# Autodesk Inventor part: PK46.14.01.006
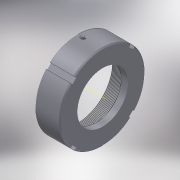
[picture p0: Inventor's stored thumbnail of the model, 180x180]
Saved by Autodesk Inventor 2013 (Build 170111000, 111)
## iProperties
Shininess: 64.0
Length Units: 11269
Angle Units: 11279
Time Units: 11290
Mass Units: 11283
Length Display Precision: 3
Angle Display Precision: 2
Compacted: True
Part Number: PK46.14.01.006
Document SubType Name: Modeling
Created: 2004-11
Material: Сталь высокопрочная низколегированная
Designer: ELarisa
Manufacturer: Standard
Standards Organization: Custom
Density: 7.84 g/cm^3
Density: 0.0
Volumn: 0.0
Area: 0.0
PropertySet Name: Model Information
Control State: 0
Master: False
Checked Out: False
Checked Out Date: 2008-10-15
Last Check In Date: 2008-10-15
Author: ELarisa
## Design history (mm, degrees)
sketch "Эскиз1"
  geometry: L1 (-22.039, -42.966)-(-22.039, 32.534); L2 (-22.039, 32.534)-(-20.039, 34.534); L3 (-20.039, 34.534)-(21.961, 34.534); L4 (21.961, 34.534)-(23.961, 32.534); L5 (23.961, 32.534)-(23.961, -42.966); L6 (23.961, -42.966)-(-22.039, -42.966); L7 (-22.039, 20.534)-(-20.039, 18.534); L8 (-20.039, 18.534)-(6.461, 18.534); L9 (6.461, 18.534)-(7.961, 20.034); L10 (7.961, 20.034)-(11.961, 20.034); L11 (11.961, 20.034)-(11.961, 3.034); L12 (11.961, 3.034)-(23.961, 3.034)
  constraints: 24 end point, 6 perpendicular, 4 parallel, 2 point on line, 1 vertical
  dimensions: "d0" = 46 distance of L5.end L1.start; "d1" = 34 distance between parallel lines of L11 L1; "d2" = 4 distance of L9.end L10.end; "d3" = 45 deg angle of L7 L1; "d4" = 2 horizontal distance of L7.start L7.end; "d5" = 2 horizontal distance of L1.end L2.end; "d6" = 135 deg angle of L2 L1 (derived); "d7" = 135 deg angle of L4 L3 (derived); "d8" = 2 horizontal distance of L3.end L4.end; "d10" = 135 deg angle of L9 L8 (derived); "d11" = 77.5 distance between parallel lines of L6 L3; "d12" = 46 distance between parallel lines of L6 L12; "d13" = 63 distance between parallel lines of L6 L10; "d14" = 61.5 distance between parallel lines of L6 L8
revolve "Вращение1" sketch "Эскиз1" stored, may be unused: angle "d15" = 90 deg
feature "Резьба1" dims "d16" = 10, "d17" = 0
node "РабОсь1"
node "РабПлоскость1"
sketch "Эскиз2"
  geometry: L1 (-31.239, -42.966)-(33.161, -42.966) reference; L2 (-22.039, -118.466)-(-22.039, 32.534) reference; 1 further point
  dimensions: "d19" = 0 distance from line of L1 point (-11.039, -42.966); "d20" = 11 distance from line of point (-11.039, -42.966) L2
hole "Отверстие1" sketch "Эскиз2" diameter "d21" = 6.647; stored, may be unused: countersink angle "d25" = 82 deg, drill point angle "d27" = 118 deg; dims "d22" = 20, "d23" = 11.2, "d24" = 2, "d26" = 20
sketch "Эскиз3"
  geometry: L1 (0, 0)-(0, -85.733); L2 (0, 0)-(-71.545, -71.545); L3 (-47.73, -54.801)-(-54.801, -47.73); L4 (-54.801, -47.73)-(-64.801, -57.73); L5 (-64.801, -57.73)-(-57.73, -64.801); L6 (-57.73, -64.801)-(-47.73, -54.801); C1 r 63.5 at (0, 0) reference; C2 r 77.5 at (0, 0) reference
  constraints: 12 end point, 3 perpendicular, 1 parallel, 1 vertical
  dimensions: "d28" = 45 deg angle of L1 L2; "d29" = 10 horizontal distance of L3.end L4.end; "d30" = 72.5 distance from line of L3 C2.centre; "d31" = 5 distance between parallel lines of L2 L4; "d32" = 5 distance between parallel lines of L6 L2
extrude "Выдавливание1" cut sketch "Эскиз3" stored distance "d33" = 10; taper "d34" = 0 deg
pattern_circular "Круговой массив1" dims angle "d37" = 360 deg
body "Solid1"
other parameters: "d18" = 77.5
